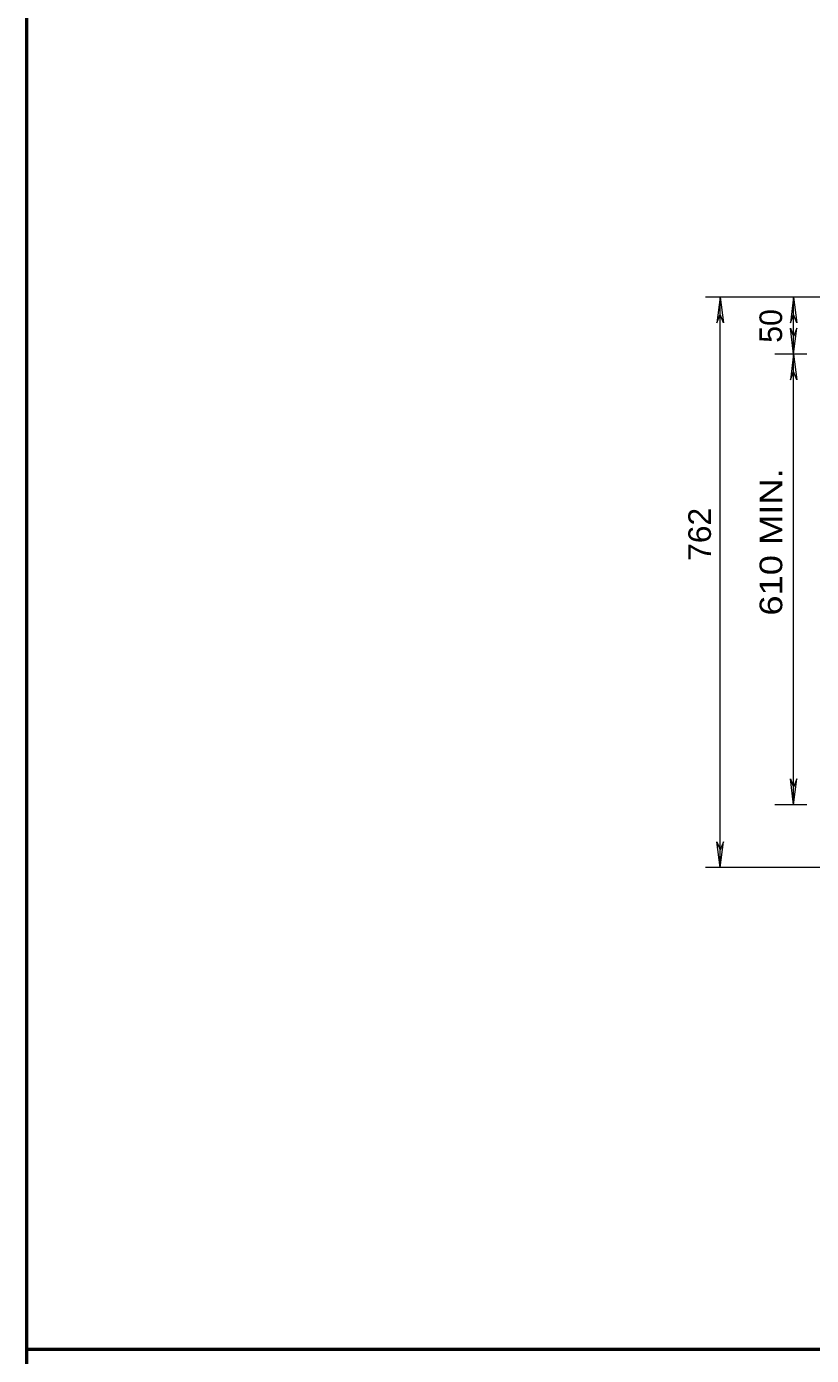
# Model space of a CAD drawing. Extents: x 312583 to 312854, y 144419 to 144597.
# Drawn here: x 312708.18 to 312734.56, y 144503.84 to 144548.48 of the extents above; entities that cross this region are included whole.
import ezdxf

# ---------------------------------------------------------------- set-up
doc = ezdxf.new("R2010")
doc.units = 0
doc.header["$LTSCALE"] = 0.3
doc.layers.add('2', color=7, linetype='Continuous', lineweight=13)

msp = doc.modelspace()

# ---------------------------------------------------------------- linework, layer by layer
at = {"layer": '2', "lineweight": 53}
for p, q in [((312708.1809, 144585.0846), (312708.1809, 144423.0846)), ((312708.1809, 144504.0495), (312849, 144504.0495))]:
    msp.add_line(p, q, dxfattribs=at)
at = {"layer": '2'}
for p, q in [((312739.917, 144539.3938), (312731.0007, 144539.3938)), ((312731.4914, 144539.3938), (312731.384, 144538.5274)), ((312731.4914, 144520.2271), (312731.4914, 144539.3938)), ((312731.4914, 144539.3938), (312731.5987, 144538.5274)), ((312733.96, 144539.3938), (312733.8527, 144538.5274)), ((312733.96, 144539.3938), (312734.0674, 144538.5274)), ((312731.384, 144538.5274), (312731.4914, 144538.8034)), ((312731.5987, 144538.5274), (312731.4914, 144538.8034)), ((312733.8527, 144538.5274), (312733.96, 144538.8034)), ((312734.0674, 144538.5274), (312733.96, 144538.8034)), ((312733.8527, 144538.3434), (312733.96, 144538.0674)), ((312733.96, 144537.4771), (312733.8527, 144538.3434)), ((312734.0674, 144538.3434), (312733.96, 144538.0674)), ((312733.96, 144537.4771), (312734.0674, 144538.3434)), ((312734.4047, 144537.4771), (312733.3314, 144537.4771)), ((312733.96, 144537.4771), (312733.8527, 144536.6108)), ((312733.96, 144537.4771), (312734.0674, 144536.6108)), ((312733.8527, 144536.6108), (312733.96, 144536.8868)), ((312734.0674, 144536.6108), (312733.96, 144536.8868)), ((312733.8527, 144523.2018), (312733.96, 144522.9258)), ((312733.96, 144522.3354), (312733.8527, 144523.2018)), ((312734.0674, 144523.2018), (312733.96, 144522.9258)), ((312733.96, 144522.3354), (312734.0674, 144523.2018)), ((312734.4047, 144522.3354), (312733.3314, 144522.3354)), ((312731.384, 144521.0934), (312731.4914, 144520.8174)), ((312731.4914, 144520.2271), (312731.384, 144521.0934)), ((312731.5987, 144521.0934), (312731.4914, 144520.8174)), ((312731.4914, 144520.2271), (312731.5987, 144521.0934)), ((312739.7407, 144520.2271), (312731.0007, 144520.2271))]:
    msp.add_line(p, q, dxfattribs=at)
msp.add_lwpolyline([(312733.96, 144522.3354), (312733.96, 144537.4771), (312733.96, 144539.3938)], dxfattribs=at)

# ---------------------------------------------------------------- texts
msp.add_text('50', height=0.76, rotation=90, dxfattribs=at).set_placement((312733.5711, 144537.856))
for s, width, p in [('610 MIN.', 1.2, (312733.5775, 144528.6896)), ('762', 1.05, (312731.1808, 144530.5294))]:
    msp.add_text(s, height=0.76, rotation=90, dxfattribs=dict(at, width=width)).set_placement(p)

doc.saveas('drawing.dxf')
